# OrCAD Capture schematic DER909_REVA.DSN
size C
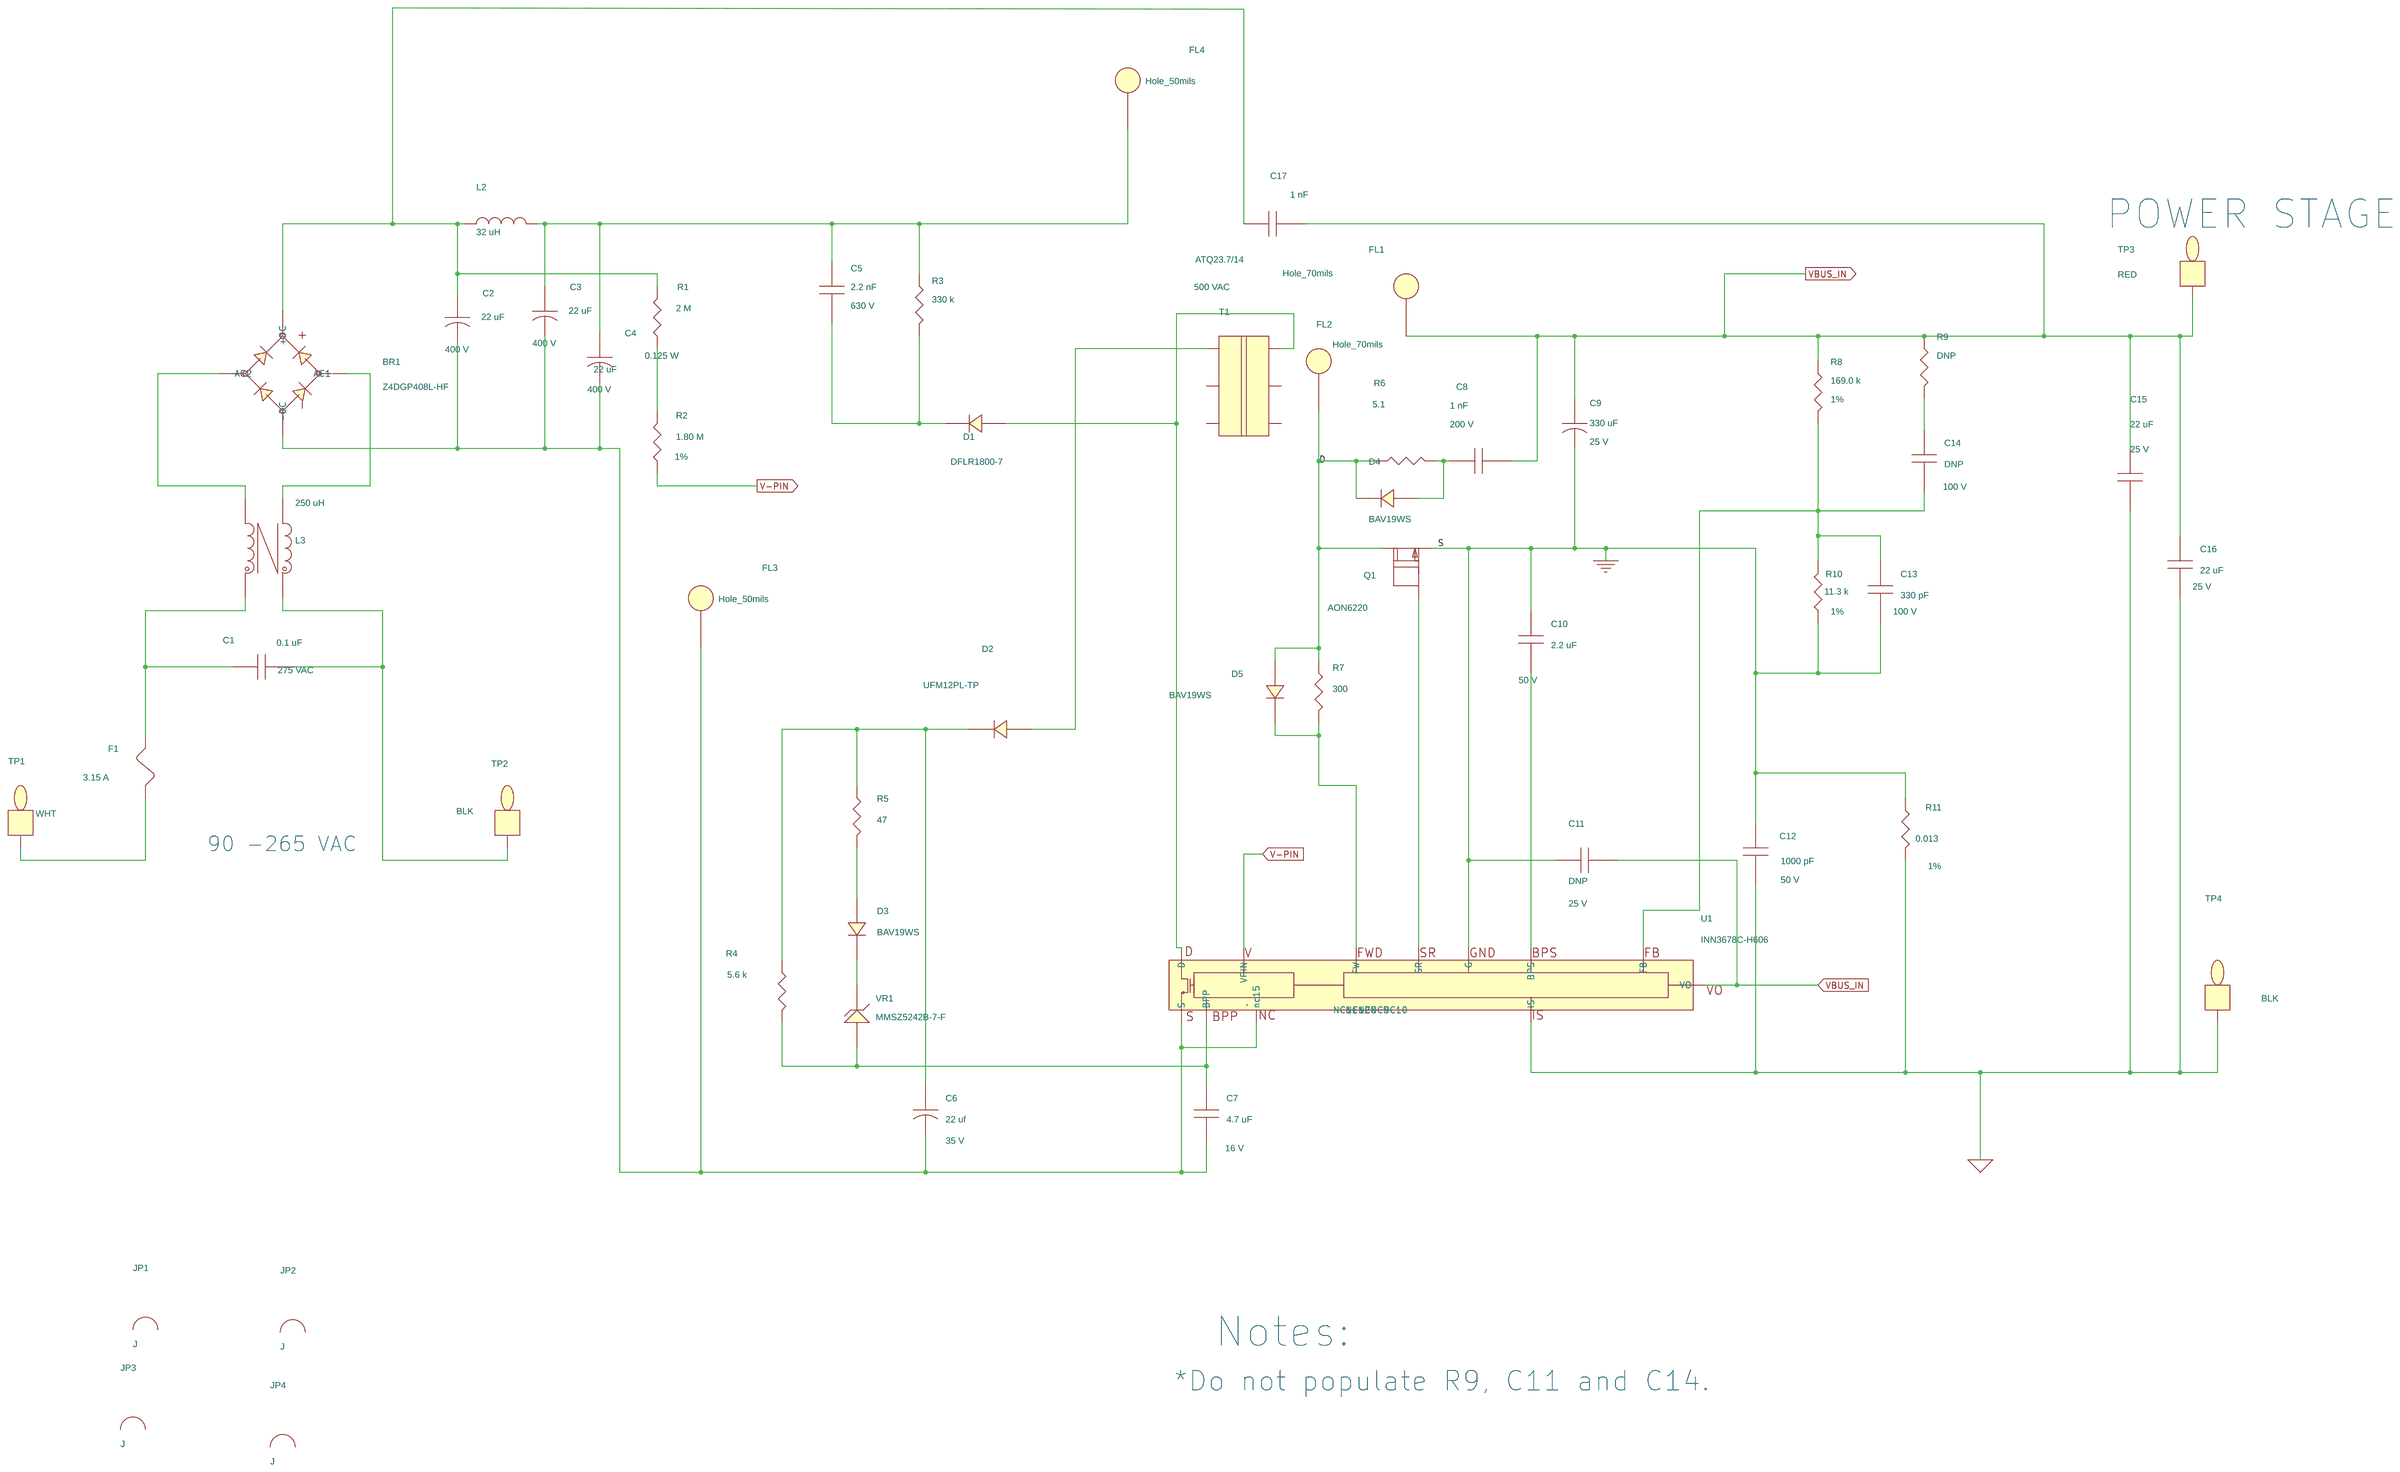
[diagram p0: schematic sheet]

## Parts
BR1  Z4DGP408L-HF  [pi_sm_d_z4d]
C1  0.1 uF  [pinpxcaprad5x13x11p1mm040]
C2  22 uF  [pipolcapclyd320ls140030]
C3  22 uF  [pipolcapclyd320ls140030]
C4  22 uF  [pipolcapclyd320ls140030]
C5  2.2 nF  [pismc1206]
C6  22 uf  [pipolcap4p0x11p0xls1p5d030]
C7  4.7 uF  [pismc0805]
C8  1 nF  [pismc0805]
C9  330 uF  [pipolcapcyld315ls138d030]
C10  2.2 uF  [pismc0805]
C11  DNP  [pismc1206]
C12  1000 pF  [pismr0402]
C13  330 pF  [pismc0402]
C14  DNP  [pismc0402]
C15  22 uF  [pismc0805]
C16  22 uF  [pismc0805]
C17  1 nF  [pi_np475x200ls395d040]
D1  DFLR1800-7  [pismddflr120012]
D2  UFM12PL-TP  [pi_sm_sod-123_12]
D3  BAV19WS  [pismsod323]
D4  BAV19WS  [pismsod323]
D5  BAV19WS  [pismsod323]
F1  3.15 A  [pi_rst_microfuse]
FL1  Hole_70mils  [pi_hole_70mil]
FL2  Hole_70mils  [pi_hole_70mil]
FL3  Hole_50mils  [pi_hole_50mil]
FL4  Hole_50mils  [pi_hole_50mil]
JP1  J  [pi_jumper700]
JP2  J  [pi_jumper500_d020]
JP3  J  [pi_jumper300_d020]
JP4  J  [pi_jumper300_d020]
L2  32 uH  [pi_2p_10D_5p5Wd40]
L3  250 uH  [pi_toroid_CMC4p_V]
Q1  AON6220  [pismpqfn5x6b]
R1  2 M  [pi18wvresd80ls100d030]
R2  1.80 M  [pismr1206]
R3  330 k  [pismr1206]
R4  5.6 k  [pismr0603]
R5  47  [pismr0603]
R6  5.1  [pi14wvresd100ls100d030]
R7  300  [pismr0603]
R8  169.0 k  [pismr0402]
R9  DNP  [pismr0402]
R10  11.3 k  [pismr0402]
R11  0.013  [pismr0805]
T1  ATQ23.7/14  [pi_bobbin_ATQ23_7_H_6P]
TP1  WHT  [pitpkeystone125x125]
TP2  BLK  [pitpkeystone125x125]
TP3  RED  [pitpkeystone125x125]
TP4  BLK  [pitpkeystone125x125]
U1  INN3678C-H606  [pi_ic_insop_24d]
VR1  MMSZ5242B-7-F  [pi_sm_sod-123_12]

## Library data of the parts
BR1 = DISCRETE_BRIDGE_+~~-: Part Number: 15-01113-00; ROOM: 1
C1 = CAP_NP: ALT_SYMBOLS: pinpxcaprad5x13x11p1mm040h; Disp_Voltage: 275 VAC; FPLIST: pinpxcaprad5x13x11p1mm040,pinpxcaprad5x13x11p1mm040h; Part Number: 20-09109-00; Voltage: 275 VAC
C2-C4 = CAP_POL: ALT_SYMBOLS: pipolcapclyd320ls140d30h750; Disp_Voltage: 400 V; FPLIST: pipolcapclyd320ls140030,pipolcapclyd320ls140d30h750; Part Number: 20-01371-00; Voltage: 400 V
C5 = CAP_NP_0: Disp_Voltage: 630 V; Part Number: 20-08609-00; ROOM: 1; Voltage: 630 V
C6 = CAP_POL: ALT_SYMBOLS: pipolcap4p0x12p5xls1p5d030h; Disp_Voltage: 35 V; FPLIST: pipolcap4p0x11p0xls1p5d030,pipolcap4p0x12p5xls1p5d030h; Part Number: 20-01139-00; ROOM: 1; Voltage: 35 V
C7 = CAP_NP: Disp_Voltage: 16 V; Part Number: 20-09166-00; ROOM: 2; Voltage: 16 V
C8 = CAP_NP: ALT_SYMBOLS: pismc0805_1; Disp_Voltage: 200 V; FPLIST: pismc0805,pismc0805_1; PCB Editor PCBFP: pismc0603; Part Number: 20-00737-00; ROOM: 2; Voltage: 200 V
C9 = CAP_POL: ALT_SYMBOLS: pipolcapcyld315ls138d030h; Disp_Voltage: 25 V; FPLIST: pipolcapcyld315ls138d030,pipolcapcyld315ls138d030h; Part Number: 20-09107-00; ROOM: 2; Voltage: 25 V
C10 = CAP_NP: Disp_Voltage: 50 V; Part Number: 20-09011-00; Voltage: 50 V
C11 = CAP_NP: Disp_Voltage: 25 V; Part Number: 20-01034-00; ROOM: 2; Voltage: 25 V
C12 = CAP_NP: ALT_SYMBOLS: pismr0402_1; Disp_Voltage: 50 V; FPLIST: pismr0402,pismr0402_1; Part Number: 20-09106-00; ROOM: 2; Voltage: 50 V
C13 C14 = CAP_NP: ALT_SYMBOLS: pismr0402_1; Disp_Voltage: 100 V; FPLIST: pismc0402,pismr0402_1; Part Number: 20-09059-00; ROOM: 2; Voltage: 100 V
C15 C16 = CAP_NP: Disp_Voltage: 25 V; Part Number: 20-09216-00; ROOM: 2; Voltage: 25 V
C17 = CAP_NP: COMPGROUP: 3; Disp_Voltage: 500 VAC; PCB Editor PCBFP: pinpycaprad540x290ls400040; Part Number: 20-01061-00; ROOM: 2; Voltage: 500 VAC
D1 = DIODE: COMPGROUP: 2; Part Number: 15-00919-00; ROOM: 1
D2 = DIODE: COMPGROUP: 1; Part Number: 16-00008-00; ROOM: 1
D3 = DIODE: Part Number: 15-00658-00; ROOM: 1
D4 = DIODE: Part Number: 15-00658-00; ROOM: 2
D5 = DIODE: Part Number: 15-00658-00
F1 = FUSE: ALT_SYMBOLS: pirstmicrofusehoz; COMPGROUP: 1; FPLIST: pi_rst_microfuse,pirstmicrofusehoz; Part Number: 40-00020-00; ROOM: 1
FL1 FL2 = FlyingLead: Part Number: 35-00282-00; ROOM: 2
FL3 FL4 = FlyingLead: Part Number: 35-00283-00
JP1 = JUMPER_1: Part Number: 65-00124-00
JP2 = JUMPER_1: Part Number: 65-00600-03
JP3 JP4 = JUMPER_1: Part Number: 65-00600-01
L2 = INDUCTOR: Part Number: 32-00405-00
L3 = TORRID_4P_12_34: ALT_SYMBOLS: pi_toroid_CMC4p_V,pi_toroid_CMC4p_V_275uH; FPLIST: pi_toroid_CMC4p_H,pi_toroid_CMC4p_V,pi_toroid_CMC4p_V_275uH; Part Number: 32-00367-00
Q1 = FET_N_SGD_123_4_5678: Part Number: 50-00276-00; ROOM: 2
R1 = R: ALT_SYMBOLS: pi18wresd080ls300d030; Disp_Power: 0.125 W; FPLIST: pi18wvresd80ls100d030,pi18wresd080ls300d030; Part Number: 05-02416-00; ROOM: 1
R2 = R: Disp_Tol: 1%; Part Number: 05-03155-00; ROOM: 1
R3 = R: Part Number: 05-01412-00; ROOM: 1
R4 = R: Part Number: 05-01706-00; ROOM: 1
R5 = R: Part Number: 05-01656-00; ROOM: 1
R6 = R: ALT_SYMBOLS: pi14wvresd100ls125d030,pi14wvresd100ls150d030,pi14wvresd100ls200d030,pi14wvresd100ls300d030,pi14wresd100ls400d030,pi14wresd100ls500d030; FPLIST: pi14wvresd100ls100d030,pi14wvresd100ls125d030,pi14wvresd100ls150d030,pi14wvresd100ls200d030,pi14wvresd100ls300d030,pi14wresd100ls400d030,pi14wresd100ls500d030; Part Number: 05-02452-00; ROOM: 2
R7 = R: Part Number: 05-01675-00; ROOM: 2
R8 = R: Disp_Tol: 1%; Part Number: 05-06060-00; ROOM: 2
R9 = R: ALT_SYMBOLS: pismr0402_1; FPLIST: pismr0402,pismr0402_1; Part Number: 05-03420-00; ROOM: 2
R10 = R: Disp_Tol: 1%; Part Number: 05-05940-00; ROOM: 2
R11 = R: Disp_Tol: 1%; Part Number: 05-06374-00
T1 = BATQ23_7_6P_GENERIC: FPLIST: pi_bobbin_ATQ23_7_H_4P,pi_bobbin_ATQ23_7_H_6P; Part Number: 25-01171-00
TP1 = TESTPOINT: Part Number: 35-00044-00
TP2 TP4 = TESTPOINT: Part Number: 35-00042-00
TP3 = TESTPOINT: Part Number: 35-00043-00
U1 = Inno3EP_P15: Part Number: 10-01050-06
VR1 = DIODE_ZENER: Part Number: 15-01090-00; ROOM: 1

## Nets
GND: C9.2 C10.1 C11.1 C12.1 C13.2 Q1.1(S) R10.1 R11.1 U1.2(G)
GND_SIGNAL: C12.2 C15.2 C16.2 R11.2 TP4.1 U1.1(IS)
VBUS_IN: C8.2 C9.1 C11.2 C15.1 C16.1 C17.2 FL1.1 R8.1 R9.1 TP3.1 U1.6(VO)
D: D4.1 D5.2 FL2.1 Q1.5(D) R6.2 R7.1
NC8: U1.8(NC8)
NC9: U1.9(NC9)
NC10: U1.10(NC10)
NC11: U1.11(NC11)
NC12: U1.12(NC12)
V-PIN: R2.1 U1.13(VPIN)
N10479111: F1.1 TP1.1
N10805923: BR1.4(-DC) C2.2 C3.2 C4.2 C6.2 C7.2 FL3.1 U1.15(nc15) U1.16(S)
N10806149: C7.1 R4.2 U1.14(BPP) VR1.2
N10809540: Q1.4(G) U1.5(SR)
N10813018: R1.1 R2.2
N10840366: C3.1 C4.1 C5.1 FL4.1 L2.2 R3.1
N10873526: D5.1 R7.2 U1.7(FW)
N10897256: C13.1 C14.2 R8.2 R10.2 U1.3(FB)
N10950053: C6.1 D2.1 R4.1 R5.1
N10966650: D1.2 T1.6 U1.24(D)
N11058959: BR1.1(+DC) C2.1 C17.1 L2.1 R1.2
N11077448: D3.2 R5.2
N11099981: C1.1 F1.2 L3.1
N11100013: C1.2 L3.3 TP2.1
N11100025: BR1.3(AC2) L3.2
N11100037: BR1.2(AC1) L3.4
N11105885: D2.2 T1.1
N11139601: C5.2 D1.1 R3.2
N11156493: C8.1 D4.2 R6.1
N11473834: D3.1 VR1.1
N11479585: C14.1 R9.2
N11512145: C10.2 U1.4(BPS)

Not connected (* = marked no-connect by the designer): JP1 1 2; JP2 1 2; JP3 1 2; JP4 1 2; Q1 2(S2) 3(S3) 6(D6) 7(D7) 8(D8); T1 2 3 4 5

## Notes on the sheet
- POWER STAGE
- 90 -265 VAC
- Notes:
- *Do not populate R9, C11 and C14.
